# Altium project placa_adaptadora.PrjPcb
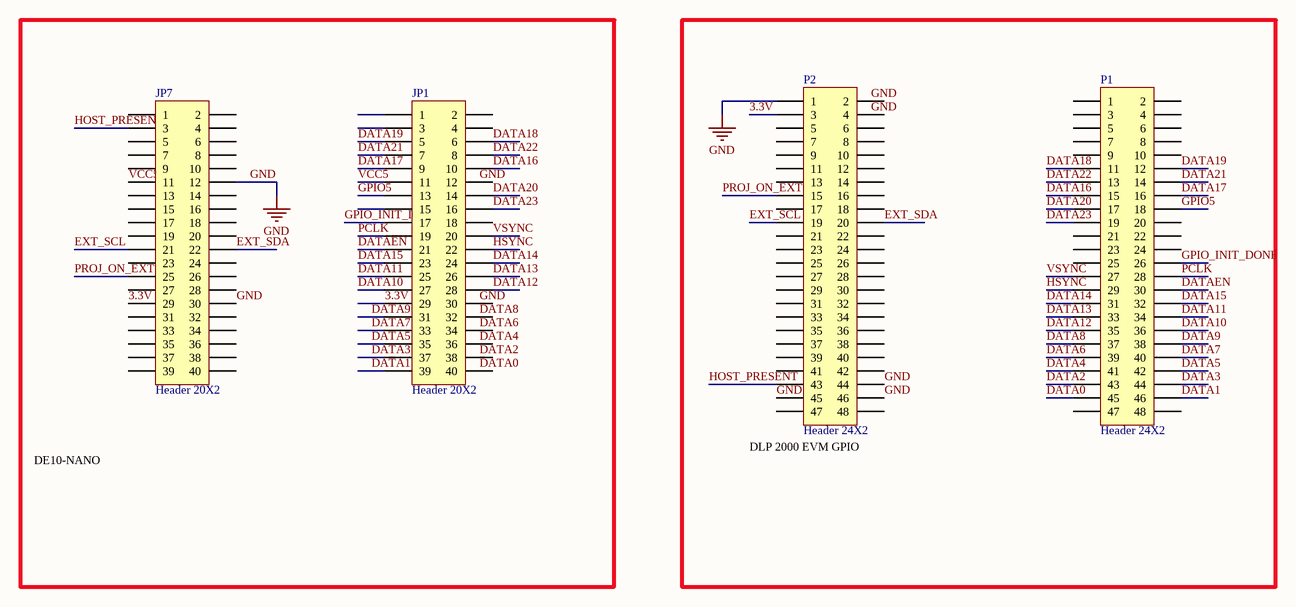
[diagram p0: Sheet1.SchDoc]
1 sheet, 4 parts. Net scope: global (net labels, ports and power ports of the same name join across sheets).
Board file: PCB1.PcbDoc

## Sheet Sheet1.SchDoc
size A4

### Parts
JP1  Header 20X2  [HDR2X20]
JP7  Header 20X2  [HDR2X20]
P1  Header 24X2  [HDR2X24]
P2  Header 24X2  [HDR2X24]

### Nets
GND: JP7.12 JP7.30 P2.1 P2.44 P2.45 P2.46
3.3V: JP1.29 JP7.29 P2.3
DATA0: P1.45
DATA1: JP1.39 P1.46
DATA2: P1.43
DATA3: JP1.37 P1.44
DATA4: P1.41
DATA5: JP1.35 P1.42
DATA6: P1.39
DATA7: JP1.33 P1.40
DATA8: P1.37
DATA9: JP1.31 P1.38
DATA10: JP1.27 P1.36
DATA11: JP1.25 P1.34
DATA12: JP1.28 P1.35
DATA13: JP1.26 P1.33
DATA14: JP1.24 P1.31
DATA15: JP1.23 P1.32
DATA16: JP1.10 P1.15
DATA17: JP1.9 P1.16
DATA18: JP1.6 P1.11
DATA19: JP1.5 P1.12
DATA20: JP1.14 P1.17
DATA21: JP1.7 P1.14
DATA22: JP1.8 P1.13
DATA23: JP1.16 P1.19
DATAEN: JP1.21 P1.30
EXT_SCL: JP7.21 P2.19
EXT_SDA: JP7.22 P2.20
GPIO5: JP1.13 P1.18
GPIO_INIT_DONE: JP1.17 P1.26
HOST_PRESENT: JP7.3 P2.43
HSYNC: JP1.22 P1.29
PCLK: JP1.19 P1.28
PROJ_ON_EXT: JP7.25 P2.15
VCC5: JP1.11 JP7.11
VSYNC: JP1.20 P1.27

Not connected (* = marked no-connect by the designer): JP1 1 2 3 4 12 15 18 30 32 34 36 38 40; JP7 1 2 4 5 6 7 8 9 10 13 14 15 16 17 18 19 20 23 24 26 27 28 31 32 33 34 35 36 37 38 39 40; P1 1 2 3 4 5 6 7 8 9 10 20 21 22 23 24 25 47 48; P2 2 4 5 6 7 8 9 10 11 12 13 14 16 17 18 21 22 23 24 25 26 27 28 29 30 31 32 33 34 35 36 37 38 39 40 41 42 47 48

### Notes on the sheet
- DE10-NANO
- DLP 2000 EVM GPIO
- Labels drawn without touching a wire or pin: DATA0, DATA2, DATA4, DATA6, DATA8, GND

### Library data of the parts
JP1 JP7 = Header 20X2: Header, 20-Pin, Dual row
P1 P2 = Header 24X2: Header, 24-Pin, Dual row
